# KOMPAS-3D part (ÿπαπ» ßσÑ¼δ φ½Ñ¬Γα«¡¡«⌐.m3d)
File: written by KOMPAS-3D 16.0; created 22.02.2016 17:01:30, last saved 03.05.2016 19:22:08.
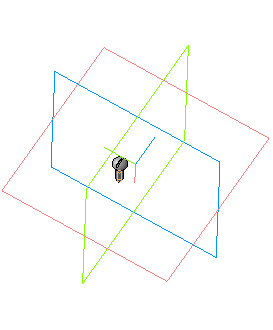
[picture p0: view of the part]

Referenced files in E:\Libs\PartLib\DATA\vault\Methods\Kompas\3D\: PLib_Screw_Shurup_900.m3d
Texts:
  Л63 ГОСТ 15527-2004
  Шуруп 1-2x10.3 ГОСТ 1144-80
  head2
  head4
  groove1
  fillet4
  head3
  groove4
  head5
  fillet1
  groove2
  groove3
  fillet2
  groove5
  head1
  (-) Шуруп 1-2x10.3 ГОСТ 1144-80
